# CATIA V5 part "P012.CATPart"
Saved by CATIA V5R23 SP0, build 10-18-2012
Part number: P012
Definition: Vis Chc M8x30.1
Description: ISO 4762 Vis Chc M8x30.1
Publications: "Mating Edge", "Axis"
Bounding box of the stored display mesh (mm): x -28 to 8, y -6.5 to 6.5, z -6.453 to 6.453
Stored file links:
  C:\wamp\www\COURS\CONCEPTION GMP1\TITRE 02-SEMESTRE 2\03-TP7-PRESSE MECANIQUE\eleve\P012.CATPart
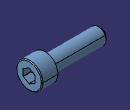
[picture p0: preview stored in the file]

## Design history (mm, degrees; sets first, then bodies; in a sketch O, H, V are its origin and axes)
Parameters
  Material = "St"
  d_dia = 8 mm
  l_nom = 28 mm
  k_head_depth_max = 8 mm
  s_nom = 6 mm
  r_min = 0.4 mm
  ds_max = 8 mm
  e = 6.86 mm
  t_min = 4 mm
  p_pitch = 1.25 mm
  Threading = 26.875 mm
  dk_max = 13 mm
  PartNumber = "ISO 4762 Vis Chc M8x30"
Body1 "PartBody" (main body)
  Sketch1 on yz-plane, origin (0, 0, 0), H (0, 1, 0), V (0, 0, 1)
    circle A1 centre (0, 0) radius 6.5
    radius A1 = 6.5 {= dk_max /2}
  Pad1: profile Sketch1, direction (1, 0, 0), length 8 {= k_head_depth_max}
  Fillet1: radius 0.4 {= r_min}, on edge [face of Pad1 | face of Pad1]
  Body2
    Sketch2 on face of Pad1, origin (8, 0, 0), H (0, 1, 0), V (0, 0, 1)
      point P1 (3, -1.7321)
      point P2 (3, 1.7321)
      point P3 (0, 3.4641)
      point P4 (-3, 1.7321)
      point P5 (-3, -1.7321)
      point P6 (0, -3.4641)
      point P7 (3, 0)
      line L1 (3, -1.7321) -> (3, 1.7321)
      line L2 (3, 1.7321) -> (0, 3.4641)
      line L3 (0, 3.4641) -> (-3, 1.7321)
      line L4 (-3, 1.7321) -> (-3, -1.7321)
      line L5 (-3, -1.7321) -> (0, -3.4641)
      line L6 (0, -3.4641) -> (3, -1.7321)
      construction line L7 (0, 0) -> (3, 0)
      construction circle A1 centre (0, 0) radius 3.4641
      construction arc A2 centre (-3, -1.7321) radius 3.4641 from (-3, 1.7321) to (0, -3.4641) cw
      construction arc A3 centre (3, 1.7321) radius 3.4641 from (0, 3.4641) to (3, -1.7321) ccw
      point P8 (-3, -1.7321)
      point P9 (3, 1.7321)
      distance L1 L4 = 6 {= s_nom}
      horizontal: L7 H
      coincidence: A1 P1, A1 P2, A1 P3, A1 P4, A1 P5, A1 P6, A2 P4, A2 P6, A2 O, P8 P5, A3 P3, A3 P1, A3 O, P9 P2
      midpoint: P7 L1
    Pad2: profile Sketch2, direction (-1, 0, 0), length 5.9769 {= t_min +(e /3.47)}
    Body3
      Sketch3 on zx-plane, origin (0, 0, 0), H (-1, 0, 0), V (0, 0, 1)
        point P1 (-2.0197, 0)
        line L1 (-2.0197, 0) -> (-4, 3.43)
        line L2 (-4, 3.43) -> (-8, 3.43)
        line L3 (-8, 3.43) -> (-8, 0)
        axis line L4 (-46.2384, 0) -> (26.3409, 0)
        reference projected line E1 (-8, -6.9227) -> (-8, 6.9227) from edge [face of Pad2 | face of Pad2]
        length L2 = 4 {= t_min}
        angle L1 L4 = 60
        distance L2 L4 = 3.43 {= e /2}
        horizontal: L2 H, L4 H
        perpendicularity: L3 L2
        fix: L4
        coincidence: L3 E1, P1 L4
      Shaft1: profile Sketch3, axis Sketch3.L4, angle 360
    Intersect1: tool Body3
  Remove1: tool Body2
  Sketch4 on xy-plane, origin (0, 0, 0), H (1, 0, 0), V (0, 1, 0)
    line L1 (0, 0) -> (0, 4)
    line L2 (0, 4) -> (-1.125, 4)
    line L3 (-1.125, 4) -> (-1.125, 3.9024)
    line L4 (-1.125, 3.9024) -> (-28, 3.9024)
    line L5 (-28, 3.9024) -> (-28, 0)
    axis line L6 (-192.3446, 0) -> (99.1594, 0)
    distance L5 L1 = 28 {= l_nom}
    distance L3 L5 = 26.875 {= Threading}
    distance L2 L6 = 4 {= ds_max /2}
    distance L4 L6 = 3.9024 {= d_dia /2.05}
    vertical: L1 V, L3 V, L5 V
    horizontal: L2 H, L4 H, L6 H
    fix: L6
  Shaft2: profile Sketch4, axis Sketch4.L6, angle 360
  Fillet2: radius 0.4 {= r_min}, on edge [face of Shaft2 | face of Pad1]
  Chamfer1: length 1.25 {= p_pitch}, angle 45, on edge [face of Shaft2 | face of Shaft2]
